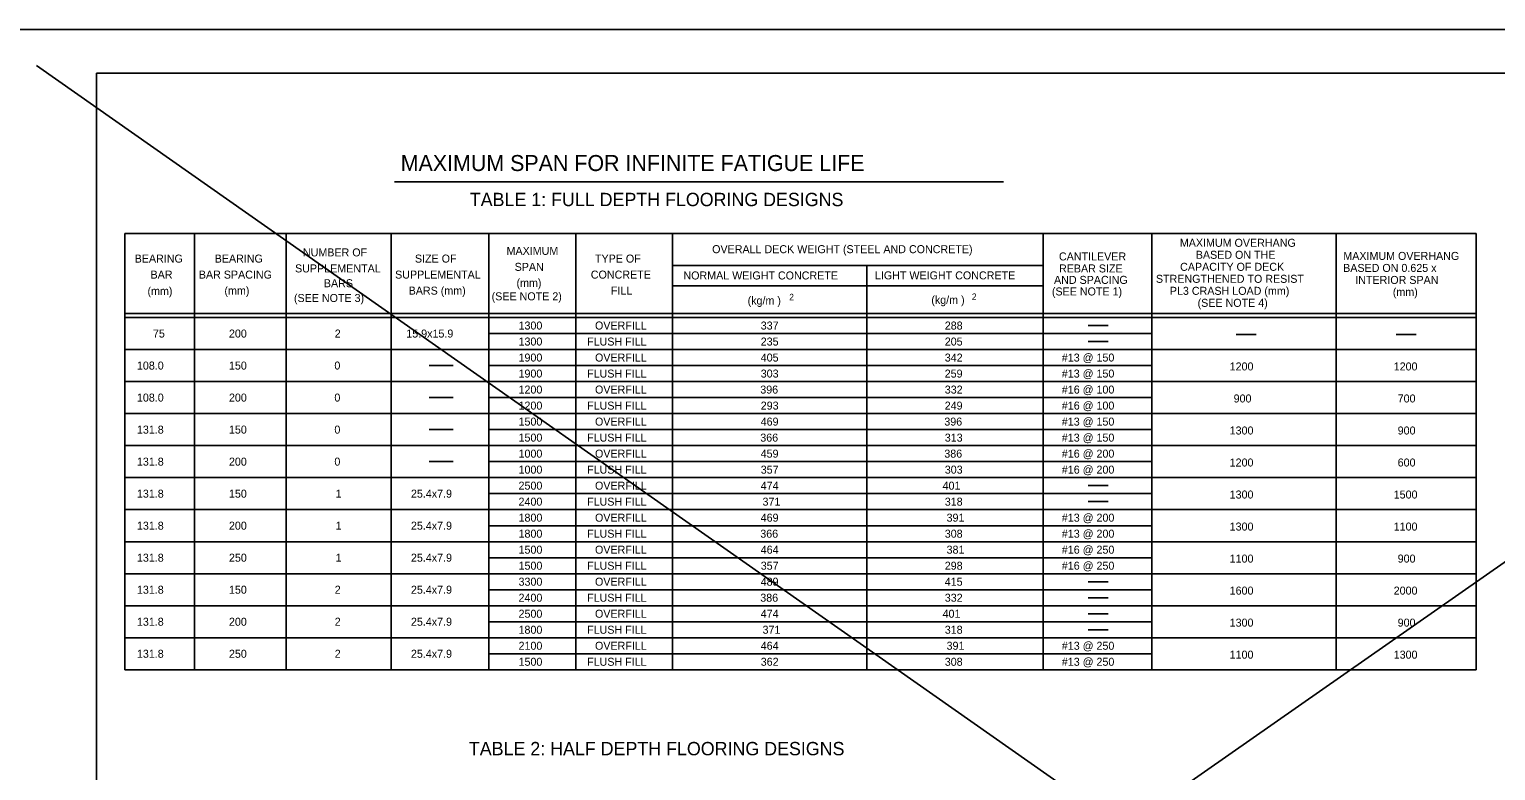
# Model space of a CAD drawing. Extents: x -24512 to -22484, y 4569 to 6351.
# Drawn here: x -23322 to -22772, y 6073 to 6351 of the extents above; entities that cross this region are included whole.
import ezdxf

# ---------------------------------------------------------------- set-up
doc = ezdxf.new("R2010")
doc.units = 0
for name, color, linetype in [('10', 7, 'Continuous'), ('2', 7, 'Continuous'), ('3', 7, 'Continuous'), ('6', 7, 'Continuous'), ('PLT-BNDY', 7, 'Continuous')]:
    doc.layers.add(name, color=color, linetype=linetype)

msp = doc.modelspace()

# ---------------------------------------------------------------- linework, layer by layer
at = {"layer": '10'}
for p, q in [((-23319.32, 6337.49), (-22508.07, 5768.63)), ((-22515.22, 6328.54), (-23306.81, 5775.78)), ((-22925, 6240.04), (-22917.5, 6240.04)), ((-22869.5, 6236.71), (-22862, 6236.71)), ((-22809.5, 6236.71), (-22802, 6236.71)), ((-22925, 6234.04), (-22917.5, 6234.04)), ((-22925, 6180.04), (-22917.5, 6180.04)), ((-22925, 6174.04), (-22917.5, 6174.04)), ((-22925, 6144.04), (-22917.5, 6144.04)), ((-22925, 6138.04), (-22917.5, 6138.04)), ((-22925, 6132.04), (-22917.5, 6132.04)), ((-22925, 6126.04), (-22917.5, 6126.04))]:
    msp.add_line(p, q, dxfattribs=at)
at = {"layer": '2'}
for p, q in [((-23296.79, 6334.63), (-22512.75, 6334.63)), ((-23296.79, 5772.04), (-23296.79, 6334.63))]:
    msp.add_line(p, q, dxfattribs=at)
at = {"layer": '3'}
for p, q in [((-23286.11, 6111.04), (-23286.11, 6274.54)), ((-23286.11, 6274.54), (-22779.5, 6274.54)), ((-23259.99, 6111.04), (-23259.99, 6274.54)), ((-23225.67, 6111.04), (-23225.67, 6274.54)), ((-23186.24, 6111.04), (-23186.24, 6274.54)), ((-23149.67, 6111.04), (-23149.67, 6274.54)), ((-23117.09, 6111.04), (-23117.09, 6274.54)), ((-23080.77, 6111.04), (-23080.77, 6274.54)), ((-22941.84, 6111.04), (-22941.84, 6274.54)), ((-22901.17, 6111.04), (-22901.17, 6274.54)), ((-22832, 6111.04), (-22832, 6274.54)), ((-22779.5, 6111.04), (-22779.5, 6274.54)), ((-22941.84, 6262.5), (-23080.77, 6262.5)), ((-23008.01, 6111.04), (-23008.01, 6262.5)), ((-22941.84, 6254.97), (-23080.77, 6254.97)), ((-23286.11, 6244.54), (-22779.5, 6244.54)), ((-23286.11, 6243.04), (-22779.5, 6243.04)), ((-23149.67, 6237.04), (-22901.17, 6237.04)), ((-23286.11, 6231.04), (-23149.67, 6231.04)), ((-23149.61, 6231.04), (-22779.5, 6231.04)), ((-23149.67, 6225.04), (-22901.17, 6225.04)), ((-23286.11, 6219.04), (-23149.67, 6219.04)), ((-23149.61, 6219.04), (-22779.5, 6219.04)), ((-23149.67, 6213.04), (-22901.17, 6213.04)), ((-23286.11, 6207.04), (-23149.67, 6207.04)), ((-23149.61, 6207.04), (-22779.5, 6207.04)), ((-23149.67, 6201.04), (-22901.17, 6201.04)), ((-23286.11, 6195.04), (-23149.67, 6195.04)), ((-23149.61, 6195.04), (-22779.5, 6195.04)), ((-23149.67, 6189.04), (-22901.17, 6189.04)), ((-23286.11, 6183.04), (-23149.67, 6183.04)), ((-23149.61, 6183.04), (-22779.5, 6183.04)), ((-23149.67, 6177.04), (-22901.17, 6177.04)), ((-23286.11, 6171.04), (-23149.67, 6171.04)), ((-23149.61, 6171.04), (-22779.5, 6171.04)), ((-23149.67, 6165.04), (-22901.17, 6165.04)), ((-23286.11, 6159.04), (-23149.67, 6159.04)), ((-23149.61, 6159.04), (-22779.5, 6159.04)), ((-23149.67, 6153.04), (-22901.17, 6153.04)), ((-23286.11, 6147.04), (-23149.67, 6147.04)), ((-23149.61, 6147.04), (-22779.5, 6147.04)), ((-23149.67, 6141.04), (-22901.17, 6141.04)), ((-23286.11, 6135.04), (-23149.67, 6135.04)), ((-23149.61, 6135.04), (-22779.5, 6135.04)), ((-23149.67, 6129.04), (-22901.17, 6129.04)), ((-23286.11, 6123.04), (-23149.67, 6123.04)), ((-23149.61, 6123.04), (-22779.5, 6123.04)), ((-23149.67, 6117.04), (-22901.17, 6117.04)), ((-23286.11, 6111.04), (-22779.5, 6111.04))]:
    msp.add_line(p, q, dxfattribs=at)
at = {"layer": '6'}
for p, q in [((-23184.99, 6293.91), (-22956.72, 6293.91)), ((-23172.11, 6225.04), (-23163.11, 6225.04)), ((-23172.11, 6225.04), (-23163.11, 6225.04)), ((-23172.11, 6213.04), (-23163.11, 6213.04)), ((-23172.11, 6201.04), (-23163.11, 6201.04)), ((-23172.11, 6189.04), (-23163.11, 6189.04))]:
    msp.add_line(p, q, dxfattribs=at)
at = {"layer": 'PLT-BNDY'}
msp.add_lwpolyline([(-23338.75, 6351.04), (-22497.75, 6351.04), (-22497.75, 5757.04), (-23338.75, 5757.04)], close=True, dxfattribs=at)

# ---------------------------------------------------------------- texts
at = {"layer": '10'}
for s, p in [('#13 @ 150', (-22934.85, 6226.54)), ('#13 @ 150', (-22934.85, 6220.54)), ('1200', (-22871.93, 6223.21)), ('1200', (-22810.43, 6223.21)), ('#16 @ 100', (-22934.85, 6214.54)), ('900', (-22870.44, 6211.21)), ('700', (-22808.94, 6211.21)), ('#16 @ 100', (-22934.85, 6208.54)), ('#13 @ 150', (-22934.85, 6202.54)), ('1300', (-22871.93, 6199.21)), ('900', (-22808.94, 6199.21)), ('#13 @ 150', (-22934.85, 6196.54)), ('#16 @ 200', (-22934.85, 6190.54)), ('1200', (-22871.93, 6187.21)), ('600', (-22808.94, 6187.21)), ('#16 @ 200', (-22934.85, 6184.54)), ('1300', (-22871.93, 6175.21)), ('1500', (-22810.43, 6175.21)), ('#13 @ 200', (-22934.85, 6166.54)), ('#13 @ 200', (-22934.85, 6160.54)), ('1300', (-22871.93, 6163.21)), ('1100', (-22810.43, 6163.21)), ('#16 @ 250', (-22934.85, 6154.54)), ('1100', (-22871.93, 6151.21)), ('900', (-22808.94, 6151.21)), ('#16 @ 250', (-22934.85, 6148.54)), ('1600', (-22871.93, 6139.21)), ('2000', (-22810.43, 6139.21)), ('1300', (-22871.93, 6127.21)), ('900', (-22808.94, 6127.21)), ('#13 @ 250', (-22934.85, 6118.54)), ('#13 @ 250', (-22934.85, 6112.54)), ('1100', (-22871.93, 6115.21)), ('1300', (-22810.43, 6115.21))]:
    msp.add_text(s, height=3, dxfattribs=at).set_placement(p)
at = {"layer": '6'}
for s, height, p in [('MAXIMUM SPAN FOR INFINITE FATIGUE LIFE', 6.0008, (-23182.71, 6297.94)), ('TABLE 1: FULL DEPTH FLOORING DESIGNS', 5, (-23156.81, 6284.78)), ('NUMBER OF', 3, (-23219.37, 6265.95)), ('MAXIMUM', 3, (-23143.03, 6266.53)), ('OVERALL DECK WEIGHT (STEEL AND CONCRETE)', 2.9999, (-23065.95, 6267.16)), ('CANTILEVER', 3, (-22935.93, 6264.44)), ('MAXIMUM OVERHANG', 2.9999, (-22890.6, 6269.55)), ('BASED ON THE', 2.9999, (-22884.63, 6265.05)), ('MAXIMUM OVERHANG', 2.9999, (-22829.32, 6264.63)), ('BEARING', 3, (-23282.46, 6263.63)), ('BEARING', 3, (-23252.46, 6263.63)), ('SUPPLEMENTAL', 2.9999, (-23222.32, 6259.95)), ('SIZE OF', 3, (-23177.39, 6263.63)), ('SPAN', 3, (-23140, 6260.53)), ('TYPE OF', 3, (-23109.89, 6263.63)), ('REBAR SIZE', 3, (-22935.91, 6259.94)), ('CAPACITY OF DECK', 2.9999, (-22890.51, 6260.55)), ('BASED ON 0.625 x', 2.9999, (-22829.38, 6260.13)), ('BAR', 3, (-23276.51, 6257.63)), ('BAR SPACING', 2.9999, (-23258.41, 6257.63)), ('BARS', 3, (-23211.52, 6254.39)), ('SUPPLEMENTAL', 2.9999, (-23184.82, 6257.63)), ('(mm)', 3, (-23139.3, 6254.53)), ('CONCRETE', 3, (-23111.44, 6257.63)), ('NORMAL WEIGHT CONCRETE', 2.9999, (-23076.72, 6257.31)), ('LIGHT WEIGHT CONCRETE', 2.9999, (-23004.92, 6257.34)), ('AND SPACING', 2.9999, (-22937.78, 6255.65)), ('STRENGTHENED TO RESIST', 2.9999, (-22899.58, 6256.05)), ('INTERIOR SPAN', 2.9999, (-22824.85, 6255.63)), ('(mm)', 3, (-23277.65, 6251.49)), ('(mm)', 3, (-23248.8, 6251.63)), ('(SEE NOTE 3)', 2.9999, (-23222.74, 6248.87)), ('BARS (mm)', 3, (-23179.74, 6251.63)), ('(SEE NOTE 2)', 2.9999, (-23148.62, 6249.49)), ('FILL', 3, (-23103.91, 6251.63)), ('(kg/m )', 3, (-23052.65, 6247.91)), ('2', 2.39, (-23037.06, 6249.53)), ('(kg/m )', 3, (-22983.78, 6248.17)), ('2', 2.39, (-22968.59, 6249.66)), ('(SEE NOTE 1)', 2.9999, (-22938.57, 6251.31)), ('PL3 CRASH LOAD (mm)', 2.9999, (-22894.36, 6251.55)), ('(mm)', 3, (-22810.76, 6251.13)), ('(SEE NOTE 4)', 2.9999, (-22883.95, 6247.05)), ('1300', 3, (-23138.54, 6238.54)), ('OVERFILL', 3, (-23109.87, 6238.54)), ('337', 3, (-23047.74, 6238.54)), ('288', 3, (-22978.74, 6238.54)), ('75', 3, (-23275.61, 6235.54)), ('200', 3, (-23247.11, 6235.54)), ('2', 3, (-23207.45, 6235.54)), ('15.9x15.9', 3, (-23180.62, 6235.54)), ('1300', 3, (-23138.54, 6232.54)), ('FLUSH FILL', 3, (-23112.84, 6232.54)), ('235', 3, (-23047.74, 6232.54)), ('205', 3, (-22978.74, 6232.54)), ('1900', 3, (-23138.54, 6226.54)), ('OVERFILL', 3, (-23109.87, 6226.54)), ('405', 3, (-23047.74, 6226.54)), ('342', 3, (-22978.74, 6226.54)), ('108.0', 3, (-23281.61, 6223.54)), ('150', 3, (-23247.11, 6223.54)), ('0', 3, (-23207.58, 6223.54)), ('1900', 3, (-23138.54, 6220.54)), ('FLUSH FILL', 3, (-23112.84, 6220.54)), ('303', 3, (-23047.74, 6220.54)), ('259', 3, (-22978.76, 6220.54)), ('108.0', 3, (-23281.61, 6211.54)), ('200', 3, (-23247.11, 6211.54)), ('0', 3, (-23207.58, 6211.54)), ('1200', 3, (-23138.54, 6214.54)), ('OVERFILL', 3, (-23109.87, 6214.54)), ('396', 3, (-23047.91, 6214.54)), ('332', 3, (-22978.74, 6214.54)), ('1200', 3, (-23138.54, 6208.54)), ('FLUSH FILL', 3, (-23112.84, 6208.54)), ('293', 3, (-23047.74, 6208.54)), ('249', 3, (-22978.76, 6208.54)), ('131.8', 3, (-23281.61, 6199.54)), ('150', 3, (-23247.11, 6199.54)), ('0', 3, (-23207.58, 6199.54)), ('1500', 3, (-23138.54, 6202.54)), ('OVERFILL', 3, (-23109.87, 6202.54)), ('469', 3, (-23047.76, 6202.54)), ('396', 3, (-22978.91, 6202.54)), ('1500', 3, (-23138.54, 6196.54)), ('FLUSH FILL', 3, (-23112.84, 6196.54)), ('366', 3, (-23047.91, 6196.54)), ('313', 3, (-22978.74, 6196.54)), ('131.8', 3, (-23281.61, 6187.54)), ('200', 3, (-23247.11, 6187.54)), ('0', 3, (-23207.58, 6187.54)), ('1000', 3, (-23138.54, 6190.54)), ('OVERFILL', 3, (-23109.87, 6190.54)), ('459', 3, (-23047.76, 6190.54)), ('386', 3, (-22978.91, 6190.54)), ('1000', 3, (-23138.54, 6184.54)), ('FLUSH FILL', 3, (-23112.84, 6184.54)), ('357', 3, (-23047.74, 6184.54)), ('303', 3, (-22978.74, 6184.54)), ('2500', 3, (-23138.54, 6178.54)), ('OVERFILL', 3, (-23109.87, 6178.54)), ('474', 3, (-23047.74, 6178.54)), ('401', 3, (-22979.56, 6178.54)), ('131.8', 3, (-23281.61, 6175.54)), ('150', 3, (-23247.11, 6175.54)), ('1', 3, (-23207.11, 6175.54)), ('25.4x7.9', 3, (-23178.88, 6175.54)), ('2400', 3, (-23138.54, 6172.54)), ('FLUSH FILL', 3, (-23112.84, 6172.54)), ('371', 3, (-23047.06, 6172.54)), ('318', 3, (-22978.74, 6172.54)), ('1800', 3, (-23138.54, 6166.54)), ('OVERFILL', 3, (-23109.87, 6166.54)), ('469', 3, (-23047.76, 6166.54)), ('391', 3, (-22978.06, 6166.54)), ('131.8', 3, (-23281.61, 6163.54)), ('200', 3, (-23247.11, 6163.54)), ('1', 3, (-23207.11, 6163.54)), ('25.4x7.9', 3, (-23178.88, 6163.54)), ('1800', 3, (-23138.54, 6160.54)), ('FLUSH FILL', 3, (-23112.84, 6160.54)), ('366', 3, (-23047.91, 6160.54)), ('308', 3, (-22978.74, 6160.54)), ('1500', 3, (-23138.54, 6154.54)), ('OVERFILL', 3, (-23109.87, 6154.54)), ('464', 3, (-23047.74, 6154.54)), ('381', 3, (-22978.06, 6154.54)), ('131.8', 3, (-23281.61, 6151.54)), ('250', 3, (-23247.11, 6151.54)), ('1', 3, (-23207.11, 6151.54)), ('25.4x7.9', 3, (-23178.88, 6151.54)), ('1500', 3, (-23138.54, 6148.54)), ('FLUSH FILL', 3, (-23112.84, 6148.54)), ('357', 3, (-23047.74, 6148.54)), ('298', 3, (-22978.74, 6148.54)), ('131.8', 3, (-23281.61, 6139.54)), ('150', 3, (-23247.11, 6139.54)), ('2', 3, (-23207.45, 6139.54)), ('25.4x7.9', 3, (-23178.88, 6139.54)), ('3300', 3, (-23138.54, 6142.54)), ('OVERFILL', 3, (-23109.87, 6142.54)), ('489', 3, (-23047.76, 6142.54)), ('415', 3, (-22978.74, 6142.54)), ('2400', 3, (-23138.54, 6136.54)), ('FLUSH FILL', 3, (-23112.84, 6136.54)), ('386', 3, (-23047.91, 6136.54)), ('332', 3, (-22978.74, 6136.54)), ('131.8', 3, (-23281.61, 6127.54)), ('200', 3, (-23247.11, 6127.54)), ('2', 3, (-23207.45, 6127.54)), ('25.4x7.9', 3, (-23178.88, 6127.54)), ('2500', 3, (-23138.54, 6130.54)), ('OVERFILL', 3, (-23109.87, 6130.54)), ('474', 3, (-23047.74, 6130.54)), ('401', 3, (-22979.56, 6130.54)), ('1800', 3, (-23138.54, 6124.54)), ('FLUSH FILL', 3, (-23112.84, 6124.54)), ('371', 3, (-23047.06, 6124.54)), ('318', 3, (-22978.74, 6124.54)), ('2100', 3, (-23138.54, 6118.54)), ('OVERFILL', 3, (-23109.87, 6118.54)), ('464', 3, (-23047.74, 6118.54)), ('391', 3, (-22978.06, 6118.54)), ('131.8', 3, (-23281.61, 6115.54)), ('250', 3, (-23247.11, 6115.54)), ('2', 3, (-23207.45, 6115.54)), ('25.4x7.9', 3, (-23178.88, 6115.54)), ('1500', 3, (-23138.54, 6112.54)), ('FLUSH FILL', 3, (-23112.84, 6112.54)), ('362', 3, (-23047.74, 6112.54)), ('308', 3, (-22978.74, 6112.54)), ('TABLE 2: HALF DEPTH FLOORING DESIGNS', 5, (-23157.16, 6078.99))]:
    msp.add_text(s, height=height, dxfattribs=at).set_placement(p)

doc.saveas('drawing.dxf')
